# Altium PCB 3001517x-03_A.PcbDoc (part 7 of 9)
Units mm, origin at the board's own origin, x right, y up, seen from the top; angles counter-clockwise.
Board outline 100 x 72 mm, 10 copper layers (Top, GND_2, Signal_3, Signal_4, PWR_5, GND_6, Signal_7, Signal_8, GND_9, Bottom), stack 1.6 mm thick; 602 components, 497 nets, 2372 pads, 1602 vias.
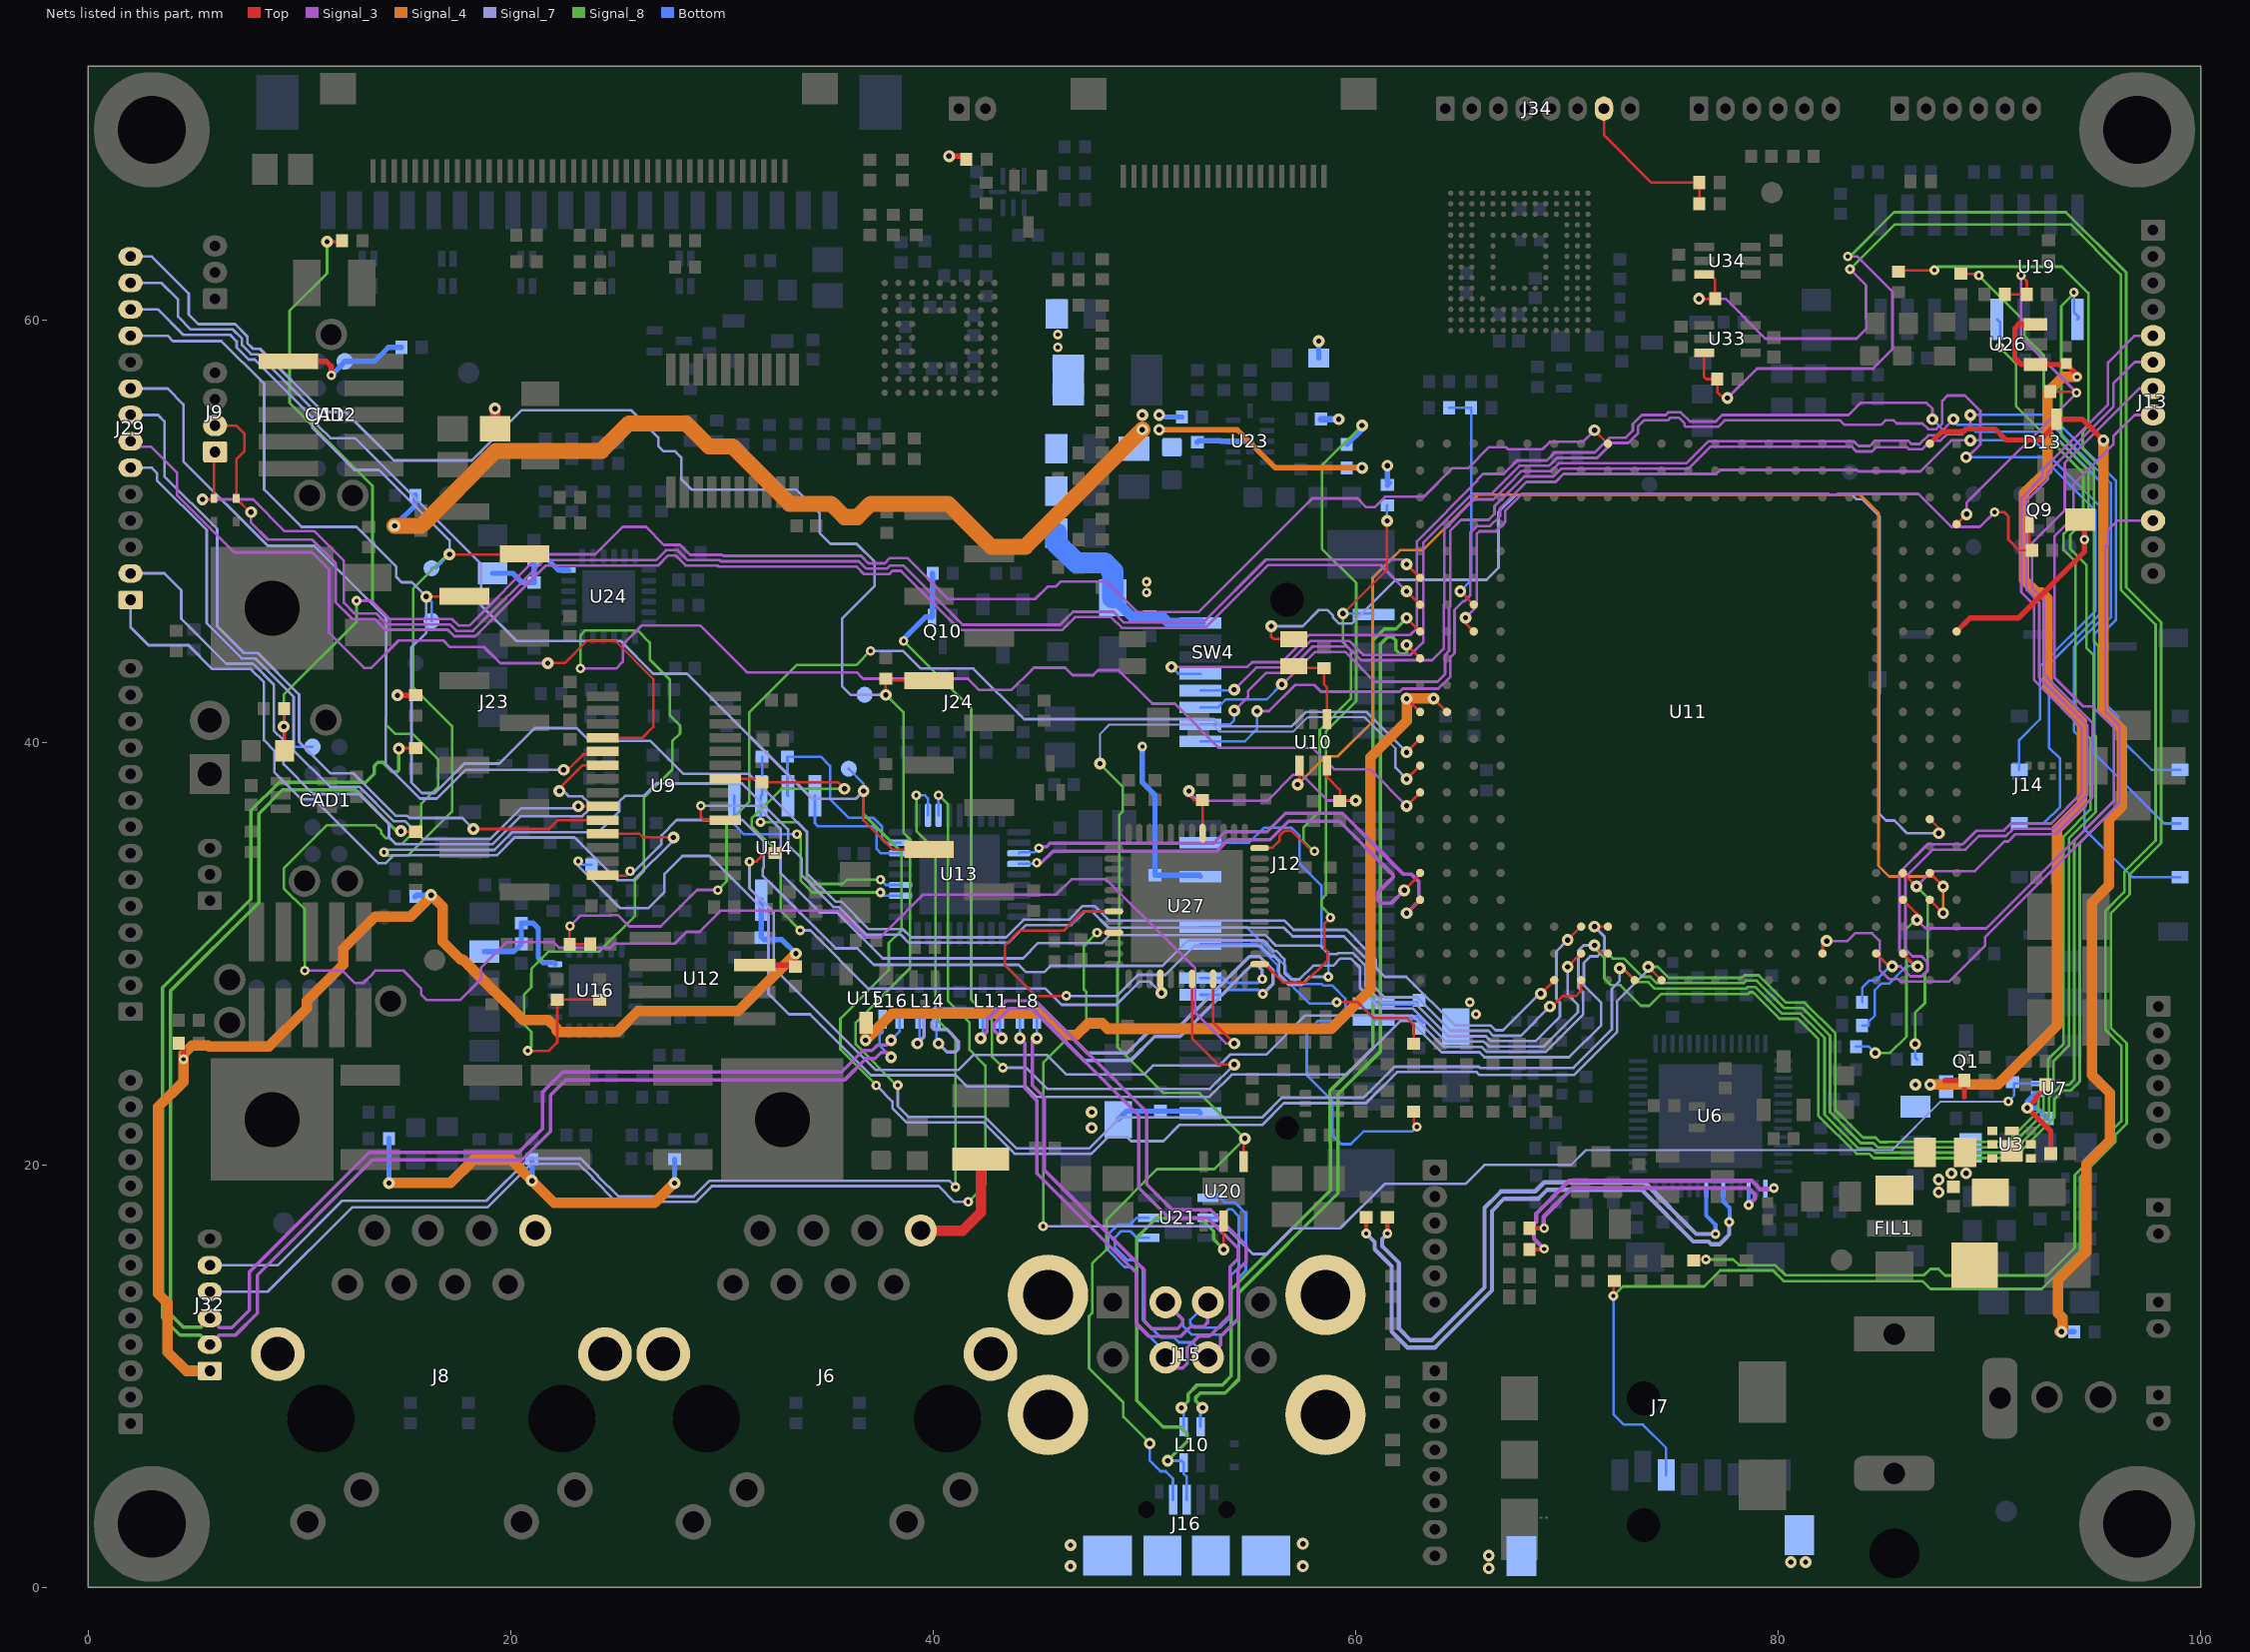
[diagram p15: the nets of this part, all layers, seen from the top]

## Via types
v1: diameter 0.56, hole 0.25, Top to Bottom, tented both sides, 1002 vias
v2: diameter 0.46, hole 0.2, Top to Bottom, tented both sides, 468 vias
v3: diameter 0.457, hole 0.2, Top to Bottom, tented both sides, 132 vias

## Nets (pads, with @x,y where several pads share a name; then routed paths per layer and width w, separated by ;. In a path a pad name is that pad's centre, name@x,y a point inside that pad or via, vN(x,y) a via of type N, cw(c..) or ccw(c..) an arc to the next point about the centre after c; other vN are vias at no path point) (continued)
OTGD_P: J16.3 L10.3 U20.5 | length 21.7
  Top w0.127: v1(53.75,16) U20.5@53.75,17.35
  Signal_8 w0.165: v1@51.101,6 52.016,6.915 52.016,7.284 51.7,7.6 50.88,7.6 49.632,8.848 49.632,16.552 50.548,17.468 52.652,17.468 53.268,16.852 53.268,16.482 v1(53.75,16)
  Bottom w0.127: v1(51.1,6) 51.75,6 L10.3@51.85,5.9 51.85,5.386 52,5.236 J16.3@52,4.15
PCIE_DIS_N/IO12: J12.20 U27.19 | length 37.3
  Top w0.119: v2(46.3,28) 44.85,28 43.4,29.45 43.4,30.4 44.1,31.1 46.2,31.1 47.1,32 U27.19@48.55,32
  Signal_7 w0.127: v2(46.3,28) 48.7,28 49.7,29 51,29 52.371,30.371 55.518,30.371 56.016,29.873 56.127,29.873 56.376,29.624 56.376,28.973 56.821,28.527 57.44,28.527 57.813,28.9 v2(58.7,28.9)
  Bottom w0.119: J12.20@52.65,35.25 54.95,35.25 55.667,35.966 56.95,35.966 57.35,35.566 57.35,34.25 58.385,33.215 58.385,30.376 58.7,30.061 v2(58.7,28.9)
PCIE_I2C_SCL: J12.30 R95.2 | length 22
  Top w0.119: R95.2@62.75,22.52 62.75,21.95 v2(62.9,21.8)
  Bottom w0.119: J12.30@52.65,31.25 54.843,31.25 56.685,29.408 56.685,29.128 57.246,28.566 58.393,28.566 58.476,28.484 58.905,28.484 59.516,27.872 59.516,27.116 59.2,26.8 58.2,26.8 57.683,26.283 57.683,24.25 58.908,23.025 58.908,21.392 59.316,20.984 59.773,20.984 60.367,21.578 62.678,21.578 v2(62.9,21.8)
PCIE_I2C_SDA: J12.32 R96.2 | length 12.8
  Top w0.119: v2(59.1,27.7) 60.1,27.7 60.85,26.95 62.443,26.95 62.75,26.643 R96.2@62.75,25.73
  Bottom w0.119: J12.32@52.65,30.45 55.295,30.45 56.3,29.445 56.3,29.15 57.816,27.634 59.033,27.634 v2(59.1,27.7)
PCIE_UIM_CLK: J12.12 J14.3 | length 72.5
  Signal_3 w0.127: v1(56.5,42.75) 56.55,42.75 58.086,44.286 59.495,44.286 60.906,42.875 63.88,42.875 64.231,43.225 64.231,44.136 64.424,44.33 64.424,46.379 64.475,46.429 64.475,50.012 64.992,50.529 66.295,50.529 66.575,50.809 66.575,51.183 67.98,52.588 69.363,52.588 69.735,52.96 75.76,52.96 76.8,54 83.475,54 83.7,53.775 84.445,53.775 84.645,53.976 86.1,53.976 86.2,53.875 86.8,53.875 87.209,54.285 87.685,54.285 88.1,54.7 88.825,54.7 89.1,54.975 v1(89.1,55.5)
  Bottom w0.119: J12.12@52.65,41.65 53.479,41.65 53.863,42.033 55.783,42.033 v1(56.5,42.75) ; v1(89.1,55.5) 92.874,55.5 96,52.374 96,45.808 95.294,45.102 95.294,42.019 96.1,41.213 96.1,40.275 97.675,38.7 J14.3@99.03,38.7
PCIE_UIM_DATA: J12.10 J14.7 | length 71.5
  Signal_3 w0.127: v1(54.25,42.5) 55.296,43.546 56.605,43.546 57.853,44.794 59.705,44.794 60.355,44.145 62.61,44.145 63.2,44.735 63.2,49.455 65.509,51.765 66.42,51.765 67.107,52.452 67.751,53.096 69.153,53.096 69.524,53.468 71.43,53.468 72.138,54.175 72.9,54.175 73.375,54.65 73.375,54.97 73.651,55.246 74.781,55.246 74.905,55.37 75.295,55.37 75.57,55.095 75.57,54.985 75.615,54.94 77.155,54.94 77.46,55.246 82.93,55.246 83.146,55.03 84.864,55.03 85.08,55.246 85.47,55.246 85.615,55.1 86.835,55.1 87.105,54.83 87.495,54.83 87.771,55.105 87.771,56.17 88.02,56.42 88.845,56.42 89.57,55.695 89.57,54.105 88.965,53.5 v1(88.9,53.5)
  Bottom w0.119: J12.10@52.65,42.45 54.2,42.45 v1(54.25,42.5) ; v1(88.9,53.5) 92.5,53.5 95.016,50.984 95.016,46.216 92.4,43.6 92.4,41.1 91.41,40.11 J14.7@91.41,38.7
PCIE_UIM_PWR: J12.8 J14.1 | length 78.5
  Signal_3 w0.127: v1(51.277,43.573) 54.873,43.573 55.1,43.8 56.5,43.8 57.786,45.086 62.586,45.086 62.9,45.4 62.9,49.515 65.755,52.369 65.755,52.43 66.03,52.706 67.002,52.706 67.646,53.35 69.048,53.35 69.419,53.722 71.325,53.722 72.033,54.429 72.795,54.429 73.121,54.755 73.121,55.075 73.545,55.5 74.675,55.5 74.8,55.624 75.4,55.624 75.83,55.194 77.05,55.194 77.355,55.5 83.334,55.5 83.905,56.07 87.03,56.07 87.3,55.8 v1(87.3,55.3)
  Bottom w0.119: v1(51.277,43.573) 51.599,43.25 J12.8@52.65,43.25 ; v1(87.3,55.3) 88.012,54.588 88.728,54.588 88.907,54.766 89.293,54.766 89.359,54.7 92.9,54.7 95.508,52.092 95.508,46.012 94,44.504 94,40.538 94.5,40.038 94.5,35.9 96.78,33.62 J14.1@99.03,33.62
PCIE_UIM_RST: J12.14 J14.2 | length 73.5
  Signal_3 w0.127: v1(54.25,41.5) 54.9,42.15 54.9,42.42 55.772,43.292 56.71,43.292 57.958,44.54 59.6,44.54 60.25,43.891 63.626,43.891 64.17,44.435 64.17,46.484 64.2,46.514 64.2,50.096 65.604,51.5 66.515,51.5 67.212,52.198 67.857,52.842 69.258,52.842 69.63,53.214 75.654,53.214 76.694,54.254 83.58,54.254 83.805,54.029 84.34,54.029 84.585,54.275 86.159,54.275 86.305,54.129 86.695,54.129 87.104,54.539 87.563,54.539 88.3,55.275 v1(88.3,55.3)
  Bottom w0.119: J12.14@52.65,40.85 54.05,40.85 54.25,41.05 v1(54.25,41.5) ; v1(88.3,55.3) 88.3,55.2 88.467,55.033 89.593,55.033 89.614,55.054 92.96,55.054 95.754,52.26 95.754,45.91 94.983,45.14 94.983,39.458 98.281,36.16 J14.2@99.03,36.16
PCIE_UIM_VPP: J12.16 J14.6 | length 72
  Signal_3 w0.127: v1(55.328,41.477) 55.893,41.477 57.137,42.72 58.037,42.72 58.358,42.4 62.075,42.4 62.22,42.546 63.91,42.546 64.485,43.12 64.485,44.031 64.678,44.225 64.678,46.274 65.089,46.685 65.15,46.685 65.426,46.96 65.426,49.89 65.424,49.891 65.424,49.924 65.665,50.166 65.674,50.166 65.749,50.241 66.365,50.241 66.829,50.704 66.829,51.078 68.085,52.334 69.469,52.334 69.84,52.706 77.078,52.706 77.273,52.9 83.734,52.9 83.805,52.829 86.729,52.829 88.2,54.3 v1(89.1,54.3)
  Bottom w0.119: J12.16@52.65,40.05 54.752,40.05 55.328,40.626 v1(55.328,41.477) ; v1(89.1,54.3) 92.1,54.3 95.262,51.138 95.262,46.114 92.821,43.673 92.821,39.758 93.35,39.229 93.35,36.95 92.56,36.16 J14.6@91.41,36.16
PCIE_VCC: C14.2 C22.2 C34.1 C35.1 C36.1 C37.2 C38.2 C39.2 C108.2 C115.2 C116.2 C117.2 C119.2 J12.2 J12.24 J12.39 J12.41 J12.52 L1.2 L29.1 R143.2 R241.2 | length 30.4
  Top w0.5: L29.1@19.25,54.85 v1(19.25,55.8)
  Bottom w0.25: C35.1@48.75,22.15 49.14,22.54 C38.2@50.75,22.54 52.56,22.54 J12.52@52.65,22.45 ; v2(49.9,39.8) 49.9,38.1 50.5,37.5 C22.2@50.5,33.71 52.59,33.71 J12.24@52.65,33.65 ; R143.2@58.25,58.2 v1(58.25,59) ; J12.41@60.85,26.85 60.85,26.982 63.018,26.982 63.2,26.8 ; J12.39@60.85,27.65 C39.2@62.86,27.65 ; R241.2@61.5,52.18 61.6,52.28 61.5,52.38 v1(61.5,53.1)
  Bottom w0.3: C108.2@58.36,55.3 v1(59.2,55.3)
  Bottom w0.5: C34.1@48.5,46.85 49.39,45.96 C37.2@50.25,45.96 50.84,45.96 51.15,45.65 J12.2@52.65,45.65
  Bottom w1: C117.2@45.825,49.9 45.825,49.455 46.78,48.5 48.1,48.5 48.5,48.1 C34.1@48.5,46.85
  other v1: 47.5,21.75 47.5,22.5
  other v2: 65.7,27.125 65.4,27.7 50.1,47.1 50.1,47.6 45.9,58.7 45.9,59.3
PCIE_VCC_EN/IO27: R141.1 U27.37 | length 33
  Top w0.125: U27.37@55.45,29.5 55.707,29.5 56.571,28.636 57.614,28.636 58.668,29.69 58.668,30.089 58.53,30.226 58.53,31.43 v3(58.8,31.7)
  Signal_8 w0.125: v3(58.8,31.7) 58.8,31.807 58.38,32.226 58.38,32.574 58.586,32.779 58.586,40.512 60.024,41.95 60.024,47.546 58.4,49.17 58.4,53.1 v1(60.3,55)
  Bottom w0.25: R141.1@59.58,54.1 60.3,54.82 v1(60.3,55)
PCIE_WAKE_N/IO38: J12.1 R241.1 U27.48 | length 23.5
  Top w0.119: U27.48@55.45,35 55.467,35.016 56.063,35.016 56.385,35.339 56.385,35.572 56.628,35.815 56.972,35.815 57.937,34.85 v3(58.05,34.85) ; v1(59.4,46.1) 61.5,48.2 61.485,48.215 v1(61.485,50.485)
  Signal_8 w0.127: v3(58.05,34.85) 57.985,34.85 57.53,35.305 57.53,35.97 58.3,36.741 58.3,40.591 59.771,42.061 59.771,44.367 59.4,44.737 v1(59.4,46.1)
  Bottom w0.119: v1(59.4,46.1) 60.8,46.1 J12.1@60.85,46.05 ; v1(61.485,50.485) 61.485,51.205 R241.1@61.5,51.22
PCM_CLK: J13.5 R192.1 U11.C20 | length 46.5
  Top w0.119: U11.C20@85.91,30.01 86.52,29.4 v1(86.6,29.4)
  Signal_3 w0.127: v1(86.6,29.4) 86.475,29.4 85.746,30.129 85.746,33.846 87.079,35.18 88.755,35.18 89.397,35.821 90.685,35.821 91.023,36.16 92.922,36.16 94.375,37.613 94.375,40.702 92.108,42.969 92.108,46.51 91.51,47.108 91.51,51.557 92.515,52.561 92.515,52.887 95.615,55.987 95.615,57.986 96.879,59.25 J13.5@97.75,59.25
  Bottom w0.119: R192.1@83.98,26.6 84.282,26.6 84.282,26.773 84.572,27.063 84.572,28.272 84.875,28.575 85.238,28.575 86.064,29.4 v1(86.6,29.4)
PCM_IN: J13.6 R195.1 U11.D20 | length 45.5
  Top w0.119: U11.D20@84.64,30.01 85.25,29.4 v1(85.4,29.4)
  Signal_3 w0.127: v1(85.4,29.4) 85.8,29.4 86.271,28.929 86.795,28.929 87.07,29.205 87.07,29.595 86.795,29.87 86.364,29.87 86.03,30.205 86.03,33.629 87.326,34.926 88.86,34.926 89.502,35.567 90.79,35.567 91.128,35.906 93.027,35.906 94.629,37.508 94.629,40.808 92.362,43.075 92.362,46.616 91.764,47.213 91.764,51.451 92.769,52.456 92.769,52.782 95.869,55.882 95.869,56.991 96.878,58 J13.6@97.75,58
  Bottom w0.119: R195.1@83.98,27.7 83.98,28.38 84.327,28.728 84.628,28.728 85.3,29.4 v1(85.4,29.4)
PCM_OUT: J13.7 R194.1 U11.C17 | length 43
  Top w0.119: U11.C17@85.91,33.82 v1(86.545,33.185)
  Signal_3 w0.127: v1(86.545,33.185) 87.27,33.91 89.309,33.91 90.713,35.313 90.895,35.313 91.234,35.652 93.132,35.652 94.883,37.403 94.883,40.913 92.616,43.18 92.616,46.721 92.018,47.319 92.018,49.421 93.57,50.973 93.57,53.224 97.096,56.75 J13.7@97.75,56.75
  Signal_8 w0.127: v1(86.485,25.725) 86.485,27.2 86.947,27.662 86.947,29.047 87.075,29.175 87.075,32.655 v1(86.545,33.185)
  Bottom w0.119: v1(86.485,25.725) 86.485,25.095 R194.1@86.58,25
PCM_SYNC: J13.8 R193.1 U11.C18 | length 44
  Top w0.119: U11.C18@85.91,32.55 86.573,31.887 v1(86.573,31.6)
  Signal_3 w0.127: v1(86.573,31.6) 86.973,31.2 89.855,31.2 95.9,37.245 95.9,40.694 94.894,41.7 94.455,41.7 93.079,43.076 93.079,49.76 93.975,50.656 93.975,52.21 95.87,54.105 95.87,54.492 96.878,55.5 J13.8@97.75,55.5
  Signal_8 w0.127: v1(84.6,25.3) 85.3,25.3 86.07,26.07 86.07,30.164 86.03,30.205 86.03,31.13 86.5,31.6 v1(86.573,31.6)
  Bottom w0.119: R193.1@83.68,25.6 84.3,25.6 v1(84.6,25.3)
POR_B: CAD1.10 R213.1 R257.1 U11.P1 | length 80
  Top w0.119: v1(9.25,40.75) 9.25,41.591 R257.1@9.259,41.6 ; R213.1@9.3,39.6 v1@9.3,40.7 ; v1(71.305,54.775) U11.P1@71.94,54.14
  Signal_3 w0.127: v3(12.7,46.7) 13.407,46.7 14.267,45.84 17.221,45.84 17.532,45.529 18.029,45.529 21.4,48.9 24,48.9 25.3,50.2 26.4,50.2 27.244,49.356 28.011,49.356 28.484,48.883 29.99,48.883 30.044,48.828 36.585,48.828 36.938,48.475 37.7,48.475 37.953,48.728 38.772,48.728 40.721,46.78 44.81,46.78 45.404,47.373 45.8,47.373 46.047,47.62 48.193,47.62 49.64,46.173 52.568,46.173 57.945,51.55 60.085,51.55 60.505,51.13 60.895,51.13 61.395,51.629 63.226,51.629 64.572,52.975 65.31,52.975 66.31,53.976 67.106,53.976 67.203,53.878 68.844,53.878 69.196,54.229 70.759,54.229 v1(71.305,54.775)
  Signal_8 w0.127: v1(9.25,40.75) 9.25,42.25 12.7,45.7 v3(12.7,46.7)
  Bottom w0.119: v1(9.25,40.75) 9.25,40.085 9.545,39.79 CAD1.10@10.615,39.79
PWR_EN/IO14: R22.2 U7.4 U27.21 | length 67.2
  Top w0.125: v2(47.75,31) U27.21@48.55,31
  Signal_8 w0.125: v2(45.2,17.1) 45.22,17.119 45.22,24.856 47.24,26.876 47.24,28.196 47.13,28.306 47.13,30.38 v2(47.75,31)
  Signal_7 w0.1: 67.6,20 70.2,20 70.9,20.7 85.4,20.7 87.7,23 v2(90.9,23)
  Signal_7 w0.125: v2(45.2,17.1) 53.809,17.1 55.127,15.782 55.782,15.782 57,17 59.277,17 61.377,19.1 65.2,19.1 66.1,20 67.6,20
  Bottom w0.1: v2(90.9,23) 91.17,23.27 R22.2@91.17,23.85
  Bottom w0.125: R22.2@91.17,23.85 U7.4@92.29,23.85
PWR_ON: Q9.G R212.2 U11.W8 | length 36
  Top w0.125: v1(65.2,45.9) 65.2,45.64 U11.W8@65.59,45.25 ; v2(90.25,50.9) 90.7,50.9 90.9,50.7 90.9,49.602 91.402,49.1 R212.2@92.02,49.1 91.9,49.22 Q9.G@91.9,50.31
  Signal_3 w0.125: v1(65.2,45.9) 65.73,46.43 65.73,49.864 65.854,49.987 66.63,49.987 67.082,50.439 67.082,50.627 67.082,50.973 67.874,51.765 82.37,51.765 82.405,51.73 82.794,51.73 82.829,51.765 86.635,51.765 88.2,50.2 89.55,50.2 v2(90.25,50.9)
QOW: J13.12 U11.F20 | length 35.7
  Top w0.125: U11.F20@82.1,30.01 82.1,30.4 v1(82.3,30.6)
  Signal_3 w0.125: v1(82.3,30.6) 83.277,30.6 83.647,30.97 84.448,30.97 84.805,30.612 84.805,29.23 85.236,28.8 85.664,28.8 85.787,28.676 88.076,28.676 89.8,30.4 89.8,30.787 96.154,37.141 96.154,40.798 95.5,41.452 95.5,49.284 95.606,49.39 95.606,50.031 96.075,50.5 J13.12@97.75,50.5
RF1_INT/NEXT: SW4.4 U11.B15 | length 53.8
  Top w0.119: v1(56,45.5) 56,45 56.115,44.885 SW4.4@57.06,44.885 ; U11.B15@87.18,36.36 87.7,35.84 87.604,35.745 v1(87.604,35.702)
  Signal_7 w0.127: v1(56,45.5) 57.492,45.5 58.263,46.27 58.653,46.27 58.928,45.995 58.928,45.906 59.205,45.629 59.829,45.629 61.901,47.701 66.201,47.701 66.764,48.264 66.764,50.914 67.577,51.727 83.488,51.727 83.705,51.511 83.989,51.511 84.8,50.7 84.8,42.315 84.78,42.295 84.78,36.625 85.105,36.3 85.5,36.3 86.1,35.7 86.102,35.702 v1(87.604,35.702)
RF_KILL: U10.4 U11.B17 U11.B18 | length 61.7
  Top w0.119: v1(57.25,38) 57.35,38.1 U10.4@57.35,38.9 ; U11.B18@87.18,32.55 v1(87.815,31.915) ; U11.B17@87.18,33.82 v1(87.815,33.185)
  Signal_4 w0.127: v1(57.25,38) 58.591,39.341 59.148,39.341 60.8,40.992 60.8,47.8 62.1,49.1 63.17,49.1 65.797,51.727 83.873,51.727 84.747,50.853 84.747,34.153 85.244,33.656 87.345,33.656 v1(87.815,33.185) v1(87.815,31.915)
RF_KILL_HW#: R231.2 SW4.3 U10.1 | length 4
  Top w0.119: SW4.3@57.06,43.615 57.155,43.52 R231.2@58.5,43.52 58.5,42.75 58.65,42.6 U10.1@58.65,41.1
RF_KILL_SW#/IO2: R232.2 R260.2 U10.6 U27.5 | length 14.4
  Top w0.119: v1(52.1,37.7) 52.1,37.5 52.33,37.27 R232.2@52.75,37.27 ; R232.2@52.73,37.25 R232.2@52.75,37.27 ; U27.5@52.75,35.7 R232.2@52.75,37.27 ; U10.6@58.65,38.9 58.65,38.35 59.25,37.75 R260.2@59.25,37.23 59.27,37.25 v1(60,37.25)
  Signal_3 w0.127: v1(52.1,37.7) 52.05,37.7 52.521,37.229 55.814,37.229 57.055,38.47 57.445,38.47 58.665,37.25 v1(60,37.25)
RS232_3_CTS_N: J29.9 U9.5 | length 37
  Top w0.119: v1(22.5,38.7) 22.7,38.7 23.425,39.425 24.2,39.425 U9.5@24.35,39.575 U9.5@24.35,39.62
  Signal_7 w0.127: J29.9@2,56.75 3.75,56.75 4.5,56 4.5,53.3 8.5,49.3 10.693,49.3 14.1,45.893 14.1,41.218 14.081,41.199 14.081,38.96 15.695,37.346 16.506,37.346 17.86,38.7 v1(22.5,38.7)
RS232_3_RTS_N: J29.8 U9.10 | length 36.2
  Top w0.119: v1(18.225,35.9) 21.8,35.9 22.225,36.325 U9.10@24.35,36.325
  Signal_7 w0.127: J29.8@2,55.5 3.3,55.5 3.6,55.2 3.6,52.6 6.1,50.1 6.1,45.5 7.367,44.232 8.011,44.232 9.974,42.269 9.974,40.026 11.47,38.53 12.555,38.53 14.56,36.524 15.1,36.524 15.2,36.424 17.701,36.424 v1(18.225,35.9)
RS232_3_RX: J29.7 U9.4 | length 38.5
  Top w0.119: v1(21.75,43.75) 22.55,43.75 23.6,44.8 24.952,44.8 26.75,43.002 26.75,40.742 26.233,40.225 U9.4@24.35,40.225
  Signal_3 w0.127: J29.7@2,54 2.95,54 4.2,52.75 4.2,51.7 6.9,49 10.6,49 11.4,48.2 11.4,45.183 13.052,43.531 13.399,43.531 14.693,44.824 16.8,44.824 17.111,44.514 18.737,44.514 19.5,43.75 v1(21.75,43.75)
RS232_3_TX: J29.6 U9.9 | length 34.5
  Top w0.119: v1(23.193,36.975) U9.9@24.35,36.975
  Signal_7 w0.127: J29.6@2,53 3,53 3.25,52.75 3.25,52.4 5.6,50.05 5.6,45.641 7.262,43.978 7.905,43.978 9.72,42.163 9.72,39.614 11.435,37.9 12.825,37.9 14.455,36.27 14.995,36.27 15.836,35.429 19.029,35.429 20.478,36.878 23.096,36.878 v1(23.193,36.975)
RS232_IOEXP_2_RX: J29.2 U9.6 | length 35.4
  Top w0.119: v1(22.3,37.7) 22.3,37.825 23.4,38.925 U9.6@24.35,38.925
  Signal_7 w0.127: J29.2@2,48 3.6,48 4.4,47.2 4.4,45.85 6.525,43.724 7.8,43.724 8.779,42.745 8.779,40.555 9.235,40.1 9.235,38.965 10.646,37.554 12.812,37.554 14.23,36.137 14.23,35.505 14.559,35.175 19.135,35.175 20.464,36.505 23.388,36.505 23.664,36.78 23.664,37.17 23.388,37.446 22.755,37.446 22.5,37.7 v1(22.3,37.7)
RS232_IOEXP_2_TX: J29.1 U9.11 | length 39.5
  Top w0.119: U9.11@24.35,35.675 26.088,35.675 26.263,35.5 v1(27.7,35.5)
  Signal_7 w0.127: J29.1@2,46.75 2,45.45 2.85,44.6 4.741,44.6 5.87,43.47 6.305,43.47 7.695,43.47 8.315,42.85 8.315,40.1 8.8,39.615 8.8,38.6 10.1,37.3 10.705,37.3 13.726,34.279 14.074,34.279 14.458,34.664 16.561,34.664 16.57,34.654 19.332,34.654 20.178,35.5 23.02,35.5 25.039,33.481 25.824,33.481 27.7,35.357 v1(27.7,35.5)
SD_CLK: R35.1 R245.2 U34.3 | length 97.1
  Top w0.119: R35.1@76,15.48 76.02,15.5 76.046,15.526 v2(76.579,15.526) ; v1(76.25,61) R245.2@77.02,61 77.02,61.905 76.775,62.15 U34.3@76.5,62.15
  Signal_3 w0.127: v1(76.25,61) 77.508,61 79.393,59.115 83.715,59.115 84.17,59.571 84.17,59.995 84.157,60.009 84.157,61.643 v2(83.4,62.4)
  Signal_8 w0.127: v2(76.579,15.526) 77.873,15.526 ; 77.874,15.525 77.899,15.5 78.145,15.254 79.868,15.254 80.343,14.779 86.914,14.779 87.205,15.07 87.595,15.07 87.903,14.762 92.73,14.762 94.038,16.07 94.038,19.52 95.703,21.184 95.703,21.519 96.246,22.062 96.246,25.645 95.496,26.395 95.496,32.021 96.387,32.912 96.387,33.862 97.875,35.351 97.875,45.575 96.223,47.227 96.223,62.143 93.843,64.522 85.522,64.522 v2(83.4,62.4)
SD_CMD: J7.3 R30.1 R243.2 U33.3 | length 116.2
  Top w0.119: v2(72.2,13.8) 72.2,14.45 R30.1@72.25,14.5 ; U33.3@76.5,58.45 76.5,57.3 76.6,57.2 R243.2@77.12,57.2 77.12,56.58 77.4,56.3 v1(77.6,56.3)
  Signal_3 w0.127: v1(77.6,56.3) 79,57.7 84.5,57.7 85.409,58.609 85.409,61.341 83.75,63 v2(83.3,63)
  Signal_8 w0.127: v2(72.2,13.8) 72.65,14.25 76.5,14.25 77.25,15 79.75,15 80.25,14.5 86.835,14.5 87.205,14.129 92.476,14.129 94.292,15.945 94.292,19.414 95.957,21.079 95.957,21.414 96.5,21.957 96.5,25.75 95.75,26.5 95.75,31.915 96.641,32.806 96.641,33.757 98.129,35.245 98.129,45.68 96.477,47.333 96.477,62.248 93.625,65.1 85.492,65.1 83.392,63 v2(83.3,63)
  Bottom w0.119: v2(72.2,13.8) 72.2,8.2 72.7,7.7 73.6,7.7 74.7,6.6 J7.3@74.7,5.325
SHLD: J6.8 J6.SHLD1 J6.SHLD2 J7.11 J7.12 J8.8 J8.SHLD1 J8.SHLD2 J15.SH1 J15.SH2 J15.SH3 J15.SH4 J16.6 J16.7 J16.8 J16.9 R55.2 | length 5.7
  Top w0.5: J6.8@39.41,16.89 41.39,16.89 42.257,17.757 42.257,20.268 R55.2@42.25,20.275
  other v1: 66.3,0.9 46.5,1 57.5,1 80.6,1.2 81.3,1.2 66.3,1.5 46.5,2 57.5,2.065
SPI1_IRQ_N: J34.7 R122.2 R273.2 | length 7.7
  Top w0.119: J34.7@71.75,70 71.75,68.75 74,66.5 R122.2@76.27,66.5 R273.2@76.27,65.5
SPKL_N: R276.1 U6.22 | length 29.6
  Top w0.2: v2(61.5,16.75) R276.1@61.5,17.52
  Signal_7 w0.2: v2(61.5,16.75) 61.247,16.497 61.247,16.153 62.05,15.35 62.05,12.25 62.6,11.7 63.6,11.7 66.1,14.2 66.1,17.966 66.781,18.647 66.884,18.75 68.5,18.75 68.925,19.175 73.679,19.175 76.125,16.729 77.029,16.729 v2(77.029,16.726)
  Bottom w0.2: U6.22@76.6,18.88 76.6,17.6 77.029,17.171 v2(77.029,16.726)
SPKL_P: R255.1 U6.20 | length 31.1
  Top w0.2: v2(60.5,16.75) R255.1@60.5,17.52
  Signal_7 w0.2: v2(60.5,16.75) 60.897,16.353 60.897,16.008 61.7,15.205 61.7,12.105 62.353,11.453 62.455,11.35 63.745,11.35 63.847,11.453 66.45,14.055 66.45,17.822 67.028,18.4 68.645,18.4 69.07,18.825 73.534,18.825 75.98,16.379 76.697,16.379 76.83,16.246 77.228,16.246 77.509,16.527 77.509,16.53 77.68,16.701 77.68,17.295 v2(77.685,17.3)
  Bottom w0.2: U6.20@77.4,18.88 77.4,18.276 77.711,17.965 77.711,17.326 v2(77.685,17.3)
SPKR_N: R278.1 U6.15 | length 15.1
  Top w0.2: R278.1@68.23,16 68.9,16 v2(68.925,16.025)
  Signal_3 w0.2: v2(68.925,16.025) 68.445,16.505 68.445,17.199 68.55,17.304 68.55,17.691 70.109,19.25 78.745,19.25 78.765,19.23 79.147,18.847 79.747,18.847 v2(79.8,18.9)
  Bottom w0.2: U6.15@79.4,18.88 79.78,18.88 v2(79.8,18.9)
SPKR_P: R277.1 U6.17 | length 13.3
  Top w0.2: R277.1@68.23,17 v2(68.925,17)
  Signal_3 w0.2: v2(68.925,17) 68.9,17.025 68.9,17.546 70.254,18.9 78.6,18.9 78.9,18.6 78.9,18.4 v2(78.6,18.1)
  Bottom w0.2: v2(78.6,18.1) U6.17@78.6,18.88
UART2_CTS_N/CAN2_TX: J24.5 J29.14 R145.2 TP12.1 U11.N21 U19.1 | length 190.4
  Top w0.119: v1(37.75,42.25) R145.2@37.75,43.02 37.845,42.925 J24.5@39.8,42.925 ; v1(72.5,29.3) 72.65,29.3 U11.N21@73.21,28.74
  Signal_8 w0.127: v1(37.75,42.25) 38.596,41.404 38.596,35.721 38.9,35.416 38.9,29.3 36.33,26.729 36.33,25.705 38.259,23.776 v3(38.324,23.776) ; v1(72.5,29.3) 72.65,29.3 73.3,28.651 73.851,28.651 74.156,28.346 78.478,28.346 78.553,28.42 78.92,28.42 80.169,27.171 81.042,27.171 82.2,26.013 82.2,22.384 83.805,20.779 84.408,20.779 84.615,20.571 85.384,20.571 85.391,20.578 91.062,20.578 92.822,22.338 92.822,23.205 93.395,23.778 93.754,23.778 94.022,24.046 94.022,35.337 95.9,37.215 95.9,40.694 95.174,41.42 95.174,44.552 94.953,44.774 94.953,52.955 93.4,54.507 93.4,60.65 94,61.25 v2(94,61.3)
  Signal_7 w0.127: J29.14@2,63 3,63 4.75,61.25 4.75,60.25 5.2,59.8 6.951,59.8 7.529,59.222 7.529,58.905 7.805,58.629 8.122,58.629 11.108,55.643 12.165,55.643 14.461,53.347 18.147,53.347 20.527,55.727 25.686,55.727 26.979,54.434 26.979,54.026 27.226,53.779 27.786,53.779 28.07,53.495 28.07,52.461 28.57,51.962 33.516,51.962 34.629,50.848 34.629,49.905 35.134,49.4 36.372,49.4 37.229,48.544 37.229,47.41 35.679,45.861 35.679,42.652 36.081,42.25 v1(37.75,42.25) ; v3(38.324,23.776) 38.324,22.782 38.836,22.27 42.465,22.27 43.955,20.78 47.38,20.78 48.846,22.246 55.568,22.246 56.5,23.178 60.378,23.178 61.847,24.647 65.827,24.647 65.88,24.594 70.309,24.594 72.126,26.411 72.126,28.334 72.5,28.708 v1(72.5,29.3)
  Bottom w0.119: 37.155,42.25 v1(37.75,42.25) ; v2(94,61.3) 94,60.365 94.25,60.115 U19.1@94.165,60.03
UART2_RTS_N/CAN2_RX: J24.9 J29.13 TP14.1 U11.M21 U19.4 | length 179.8
  Top w0.119: v1(36.7,37.7) 36.684,37.684 36.684,36.316 38.075,34.925 J24.9@39.8,34.925 ; v1(73.845,29.375) U11.M21@74.48,28.74
  Signal_8 w0.127: v1(36.7,37.7) 36.679,37.68 36.679,36.621 38.5,34.8 38.5,31.1 37.9,30.5 37.9,29.225 35.6,26.925 35.6,25.465 v3(37.3,23.765) ; v1(73.845,29.375) 74.3,29.375 74.821,28.854 78.268,28.854 78.389,28.975 79.084,28.975 80.38,27.679 81.252,27.679 82.708,26.224 82.708,22.594 84.016,21.287 84.619,21.287 84.826,21.079 85.174,21.079 85.181,21.086 90.852,21.086 92.314,22.548 92.314,23.416 92.776,23.878 92.776,25 93.514,25.738 93.514,35.547 94.782,36.816 94.782,40.19 94.079,40.893 94.079,48.551 93.516,49.114 93.516,49.87 94.445,50.798 94.445,52.744 91.261,55.928 91.261,56.061 91.262,56.062 91.262,57.938 v3(90.5,58.7)
  Signal_7 w0.127: J29.13@2,61.75 3.45,61.75 4.25,60.95 4.25,60.15 4.854,59.546 6.846,59.546 7.275,59.117 7.275,58.8 7.7,58.375 8.017,58.375 10.854,55.538 10.854,55.005 11.459,54.4 12.619,54.4 18.6,48.419 18.6,46.475 20.275,44.8 25.2,44.8 26.744,43.256 28.342,43.256 34.268,37.33 36.33,37.33 v1(36.7,37.7) ; v3(37.3,23.765) 38.07,22.995 38.07,22.676 38.731,22.016 42.359,22.016 43.85,20.526 47.485,20.526 48.259,21.3 49.2,21.3 49.371,21.13 50.895,21.13 51.658,21.893 55.574,21.893 56.605,22.924 60.483,22.924 61.952,24.393 65.721,24.393 65.862,24.252 70.327,24.252 72.38,26.306 72.38,27.762 73.845,29.227 v1(73.845,29.375)
  Bottom w0.119: TP14.1@36,38.75 36.7,38.05 v1(36.7,37.7) ; U19.4@90.355,60.03 90.5,59.885 v3(90.5,58.7)
UART2_RX: J23.2 J29.12 TP10.1 U11.R21 | length 110.8
  Top w0.119: v1(17.1,48.9) 20.675,48.9 J23.2@20.65,48.925 ; v1(69.2,27.5) 69.303,27.5 69.803,28 70.438,28 70.67,28.232 U11.R21@70.67,28.74
  Signal_8 w0.127: v2(14,34.8) 14,34.702 13.949,34.651 15.141,34.651 17.22,36.73 17.22,40.779 15.375,42.625 15.375,47.275 17,48.9 v1(17.1,48.9)
  Signal_7 w0.127: J29.12@2,60.5 3.292,60.5 4.5,59.292 6.708,59.292 7.021,58.979 7.021,58.695 7.595,58.121 7.879,58.121 10.6,55.4 10.6,54.9 12.6,52.9 13.76,52.9 17.1,49.56 v1(17.1,48.9) ; v2(14,34.8) 14.118,34.918 16.666,34.918 16.676,34.908 19.226,34.908 20.072,35.754 24.154,35.754 25.13,36.729 25.13,37.195 25.405,37.47 26.3,37.47 26.88,38.05 30.953,38.05 33.129,35.874 33.129,35.145 33.776,34.499 33.776,33.7 35.267,32.208 35.535,32.208 36.843,30.9 38.465,30.9 38.849,30.516 43.552,30.516 44.387,31.352 46.532,31.352 47.176,31.995 47.524,31.995 48.287,31.233 56.601,31.233 57.013,30.82 59.438,30.82 60.708,29.551 60.708,28.592 61.371,27.929 62.902,27.929 64.483,26.348 66.278,26.348 66.511,26.116 67.815,26.116 v1(69.2,27.5)
  Bottom w0.119: TP10.1@16.25,48.25 16.45,48.25 v1(17.1,48.9)
UART2_TX: J23.3 J29.11 TP11.1 U11.T21 | length 99.6
  Top w0.119: v1(16,46.9) 17.775,46.9 J23.3@17.8,46.925 ; v1(68.765,28.105) U11.T21@69.4,28.74
  Signal_7 w0.127: J29.11@2,59.25 3.75,59.25 4,59 6.3,59 8.321,56.979 8.321,51.968 10.089,50.2 12.7,50.2 14.581,48.319 14.581,47.826 14.826,47.581 15.319,47.581 v1(16,46.9) 16,45.2 15.3,44.5 15.3,38.1 15.8,37.6 16.4,37.6 17.8,39 19.45,39 21.125,40.675 23.12,40.675 23.72,40.075 26.606,40.075 28.172,38.509 31.285,38.509 34.03,35.765 34.03,33.805 35.373,32.462 35.64,32.462 36.948,31.154 38.571,31.154 38.954,30.77 43.447,30.77 44.282,31.606 46.427,31.606 47.071,32.249 47.629,32.249 48.311,31.568 56.625,31.568 57.063,31.129 59.571,31.129 60,30.7 60,30.678 60.962,29.716 60.962,29.316 61.373,28.905 62.395,28.905 64.698,26.602 66.383,26.602 66.616,26.37 66.964,26.37 68.7,28.105 v1(68.765,28.105)
  Bottom w0.119: v1(16,46.9) 16.25,46.65 TP11.1@16.25,45.75
UART3_CTS_N/CAN1_TX: R77.1 R125.1 U11.P19 | length 141.3
  Top w0.119: v1(71.305,31.28) U11.P19@71.94,31.28 ; R77.1@88.65,62.18 89.42,62.18 v2(89.5,62.1)
  Signal_8 w0.127: v1(71.305,31.28) 71.776,30.81 71.776,30.166 72.171,29.77 72.695,29.77 73.561,28.905 73.956,28.905 74.261,28.6 78.373,28.6 78.495,28.721 78.979,28.721 80.275,27.425 81.147,27.425 82.454,26.118 82.454,22.489 83.911,21.033 84.513,21.033 84.72,20.825 85.279,20.825 85.286,20.832 90.957,20.832 92.568,22.443 92.568,23.311 93.03,23.773 93.03,24.895 93.768,25.633 93.768,35.442 95.036,36.711 95.036,40.295 94.92,40.411 94.92,44.146 94.6,44.467 94.6,48.389 93.827,49.162 93.827,49.822 94.699,50.693 94.699,52.849 92.578,54.97 92.578,58.322 91.661,59.239 91.661,59.939 v2(89.5,62.1)
  Signal_7 w0.127: v3(23.193,34.375) 23.193,34.148 25.189,32.152 26.507,32.152 27.274,32.919 27.274,33.769 28.126,34.62 29.416,34.62 32.2,31.837 32.2,28.1 33.17,27.13 34.17,27.13 37.054,24.246 41.054,24.246 41.58,23.72 44.379,23.72 44.877,23.223 53.08,23.223 54.132,24.275 59.574,24.275 62.12,26.82 62.574,26.82 64.062,25.332 65.857,25.332 66.09,25.1 70.1,25.1 71.62,26.62 71.62,27.68 70.8,28.5 70.8,29.565 71.105,29.87 71.45,29.87 71.785,30.206 71.785,30.8 v1(71.305,31.28)
  Bottom w0.119: v3(23.193,34.375) 23.368,34.2 R125.1@23.82,34.2
UART3_RTS_N/CAN1_RX: R123.1 R155.1 U11.P20 | length 136.2
  Top w0.119: v2(31.3,34.35) 31.6,34.35 32.02,34.77 R155.1@32.5,34.77 ; v1(71.305,30.391) 71.686,30.01 U11.P20@71.94,30.01 ; R123.1@85.7,62.28 85.77,62.35 v2(87.4,62.35)
  Signal_8 w0.127: v1(71.305,30.391) 71.305,30.277 71.776,29.807 71.776,29.6 71.775,28.825 72.092,28.508 72.527,28.508 73.505,27.53 73.895,27.53 74.457,28.092 78.584,28.092 78.658,28.166 78.815,28.166 80.064,26.917 80.936,26.917 81.904,25.95 81.904,25.295 81.9,25.291 81.9,22.325 83.7,20.525 84.303,20.525 84.51,20.317 85.49,20.317 85.497,20.324 91.167,20.324 93.076,22.233 93.076,23.1 93.5,23.524 93.859,23.524 94.276,23.941 94.276,35.231 96.154,37.11 96.154,40.8 95.428,41.525 95.428,44.657 95.207,44.879 95.207,53.11 94.422,53.895 94.422,54.705 94.688,54.971 94.688,61.269 93.436,62.52 87.571,62.52 v2(87.4,62.35)
  Signal_7 w0.127: v2(31.3,34.35) 31.3,33.096 32.454,31.942 32.454,29.311 37.265,24.5 41.2,24.5 41.9,25.2 45.4,25.2 46.32,24.28 49.98,24.28 50.4,24.7 53.535,24.7 54.055,25.22 55.767,25.22 57.621,27.074 62.679,27.074 64.168,25.586 65.962,25.586 66.195,25.354 69.007,25.354 70.774,27.121 70.774,28.166 70.546,28.395 70.546,30.146 70.791,30.391 v1(71.305,30.391)
UART3_RX: U9.19 U11.R19 | length 55
  Top w0.119: v2(29,37) 29,36.465 29.14,36.325 U9.19@30.15,36.325 ; v1(70.035,30.645) U11.R19@70.67,31.28
  Signal_7 w0.127: v2(29,37) 31.645,37 32.78,35.865 32.78,33.805 34.631,31.954 35.43,31.954 37.604,29.78 44.255,29.78 44.975,30.5 48,30.5 48.379,30.879 55.729,30.879 56.226,30.381 58.325,30.381 58.726,29.98 59.124,29.98 59.169,30.024 59.875,30.024 60.454,29.446 60.454,28.487 61.265,27.675 62.797,27.675 64.378,26.094 66.173,26.094 66.405,25.862 68.512,25.862 69.67,27.02 69.67,27.695 69.5,27.865 69.5,30.11 v1(70.035,30.645)
UART3_TX: U9.14 U11.R20 | length 59.9
  Top w0.119: U9.14@24.35,33.725 24.375,33.7 25.45,33.7 v3(25.65,33.9) ; v1(70.035,29.375) U11.R20@70.67,30.01
  Signal_7 w0.127: v3(25.65,33.9) 25.85,33.9 27.135,35.185 27.135,35.6 27.859,36.324 30.961,36.324 31.981,35.304 31.981,34.076 31.929,34.024 31.929,33.676 32.176,33.43 32.205,33.43 35.384,30.25 36.415,30.25 37.195,29.47 44.05,29.47 44.396,29.125 45.254,29.125 45.549,29.42 50.85,29.42 52.054,30.625 55.624,30.625 56.121,30.127 56.232,30.127 56.63,29.73 56.63,29.078 56.926,28.781 57.335,28.781 57.985,29.431 58.935,29.431 59.274,29.77 59.77,29.77 60.2,29.34 60.2,28.382 61.186,27.396 62.717,27.396 64.273,25.84 66.068,25.84 66.3,25.608 68.902,25.608 70.52,27.226 70.52,27.58 70.035,28.065 v1(70.035,29.375)
UART5_RX: D6.2 J9.2 U11.AA7 | length 70.6
  Top w0.119: J9.2@6,55 7,55 7.4,54.6 7.4,53.8 7,53.4 D6.2@7,51.55 7.65,50.9 v1(7.7,50.9) ; v1(62.415,47.155) U11.AA7@63.05,46.52
  Signal_3 w0.127: v1(7.7,50.9) 7.7,50.4 8.5,49.6 10.6,49.6 11.7,48.5 11.7,46.641 12.495,45.846 13.543,45.846 14.056,45.332 17.01,45.332 17.321,45.021 18.315,45.021 21.664,48.371 26.975,48.371 27.452,48.848 27.801,48.848 28.274,48.375 29.779,48.375 29.833,48.32 36.374,48.32 36.727,47.967 37.91,47.967 38.063,48.12 38.474,48.12 41.279,45.315 46.102,45.315 46.715,45.928 48.425,45.928 48.934,45.42 52.88,45.42 55.861,48.4 61.17,48.4 v1(62.415,47.155)
UART5_TX: D7.2 J9.1 U11.AA6 | length 69.4
  Top w0.119: v1(5.4,51.5) 5.9,51.5 D7.2@5.95,51.55 5.95,53.7 J9.1@6,53.75 ; v1(62.415,48.425) U11.AA6@63.05,47.79
  Signal_3 w0.127: v1(5.4,51.5) 7.8,51.5 9.3,50 10.7,50 12.1,48.6 12.1,46.6 12.6,46.1 13.648,46.1 14.162,45.586 17.116,45.586 17.427,45.276 18.21,45.276 21.559,48.625 26.87,48.625 27.347,49.102 27.906,49.102 28.379,48.629 29.885,48.629 29.939,48.574 36.479,48.574 36.832,48.221 37.805,48.221 37.959,48.375 38.578,48.375 41.385,45.569 45.997,45.569 46.61,46.182 48.531,46.182 49.04,45.674 52.775,45.674 55.756,48.654 62.186,48.654 v1(62.415,48.425)
UART_PWR/IO18: R127.2 U9.22 U27.28 | length 36.3
  Top w0.119: U9.22@30.15,38.275 31.745,38.275 R127.2@31.9,38.12 35.48,38.12 v1(35.8,37.8)
  Signal_8 w0.127: v2(33.7,31.1) 32.78,32.02 32.78,34.676 31.405,36.051 31.405,36.399 32.805,37.8 v1(35.8,37.8)
  Signal_7 w0.127: v2(33.7,31.1) 34.175,31.1 36.929,28.346 45.313,28.346 46.08,27.579 48.664,27.579 49.76,28.675 50.264,28.675 v1(50.8,28.139)
USB_OTG_D_N: L10.1 U11.AA9 | length 44.8
  Top w0.127: v1(62.415,44.615) U11.AA9@63.05,43.98
  Signal_8 w0.165: v1(52.75,8.5) 52.434,8.816 52.434,9 52.634,9.2 53.82,9.2 54.468,9.848 54.468,13.948 59.168,18.648 59.168,21.21 59.16,21.218 59.16,23.36 61.181,25.381 61.181,43.762 61.181,44.663 61.518,45 61.725,45 61.9,44.825 61.9,44.375 62.1,44.175 62.325,44.175 62.415,44.265 v1(62.415,44.615)
  Bottom w0.127: L10.1@52.65,7.6 52.65,8.4 v1(52.75,8.5)
USB_OTG_D_P: L10.4 U11.AA8 | length 44.7
  Top w0.127: v1(62.415,45.885) U11.AA8@63.05,45.25
  Signal_8 w0.165: v1(51.75,8.5) 52.066,8.816 52.066,9.152 52.482,9.568 53.668,9.568 54.1,10 54.1,14.1 58.8,18.8 58.8,21.058 58.792,21.066 58.792,23.513 60.813,25.534 60.813,44.816 61.366,45.368 61.898,45.368 v1(62.415,45.885)
  Bottom w0.127: v1(51.75,8.5) 51.85,8.4 L10.4@51.85,7.6
USB_OTG_ID: J16.4 U11.AA13 U20.1 | length 65.6
  Top w0.125: U20.1@54.7,20.15 54.7,21.2 v1(54.75,21.25) ; v1(62.415,38.265) U11.AA13@63.05,38.9
  Signal_8 w0.125: v1(47.9,39) 47.9,38.97 48.846,38.024 48.849,38.024 48.97,37.904 48.97,36.72 48.815,36.565 48.815,30.17 48.814,29.62 48.722,29.528 48.722,25.569 50.891,23.4 52.6,23.4 v1(54.75,21.25) 53.3,19.8 50.6,19.8 48.2,17.4 48.2,16 47.525,15.325 47.525,12.982 47.374,12.832 47.374,10.376 49,8.75 49,8.065 v1(50.25,6.815)
  Signal_7 w0.1: v1(47.9,39) 47.9,40.4 48.349,40.849 53.208,40.849 53.542,40.514 57.053,40.514 57.717,41.178 57.778,41.178 57.8,41.2 60.4,41.2 61.88,39.72 61.88,38.8
  Signal_7 w0.125: 61.88,38.8 v1(62.415,38.265)
  Bottom w0.125: v1@50.25,6.75 50.25,5.999 50.747,5.502 50.998,5.502 51.35,5.15 J16.4@51.35,4.15
USB_OTG_OC: R16.2 R118.1 U11.AA14 | length 81.3
  Top w0.125: v2(20.8,25.4) 21.8,25.4 22.2,25.8 R118.1@22.2,27.82 R16.2@24.2,27.82 ; v1(62.415,36.995) U11.AA14@63.05,37.63
  Signal_3 w0.125: v2(23.3,43.5) 24.987,43.5 25.3,43.813 25.3,44.632 26.206,45.538 28.962,45.538 31.181,43.319 36.374,43.319 36.619,43.074 36.675,43.018 41.638,43.018 42.18,42.476 43.695,42.476 44.646,43.428 44.67,43.452 44.756,43.538 46.249,43.538 46.606,43.18 47.574,43.18 47.813,43.419 48.781,43.419 50.02,42.18 50.369,41.831 51.439,41.831 53.533,39.738 57.97,39.738 58.974,38.734 60.677,38.734 v1(62.415,36.995)
  Signal_8 w0.125: v2(20.8,25.4) 20.97,25.57 20.97,26.301 20.628,26.642 20.628,28.064 20.97,28.406 20.97,29.062 20.98,29.072 20.98,29.274 21.807,30.1 24.193,30.1 25.876,31.783 25.876,33.476 26.3,33.9 26.3,37.358 27.643,38.701 27.643,40.052 28.018,40.427 28.018,40.773 28,40.791 28,40.826 27.526,41.299 27.526,42.98 26.58,43.926 26.58,44.72 26,45.3 23.525,45.3 23.3,45.075 v2(23.3,43.5)
USB_OTG_PWR: R15.1 R80.1 U11.AA12 | length 54.8
  Top w0.125: v2(22.8,31.3) 22.78,31.28 R80.1@22.78,30.436 22.794,30.45 R15.1@23.77,30.45 ; v1(62.415,39.535) U11.AA12@63.05,40.17
  Signal_3 w0.125: v2(22.8,31.3) 23.293,31.793 24.7,31.793 24.726,31.819 25.074,31.819 25.6,31.293 27.1,31.293 28.58,32.774 28.826,33.019 29.174,33.019 29.78,33.019 v2(29.8,33)
  Signal_8 w0.125: v2(29.8,33) 30.217,33.417 30.217,36.117 31.292,37.192 31.292,41.428 33.537,43.673 36.373,43.673 v2(37.032,44.332)
  Signal_7 w0.125: v2(37.032,44.332) 38.568,44.332 39.4,43.5 41.9,43.5 44.3,41.1 53.295,41.1 53.642,40.754 56.954,40.754 57.64,41.44 60.511,41.44 v1(62.415,39.535)
USB_OTG_VBUS: U11.AA11 U11.Y11 U15.D | length 44.3
  Top w0.125: v1(62.415,42.075) U11.AA11@63.05,41.44 ; v1(63.685,42.075) U11.Y11@64.32,41.44
  Top w0.5: v1(36.8,25.9) 36.8,26.7 U15.D@36.825,26.725
  Signal_4 w0.5: v1(36.8,25.9) 38.057,27.157 45.214,27.157 46.228,26.143 46.772,26.143 47.335,26.706 47.994,26.706 48.257,26.443 58.843,26.443 60.7,28.3 60.7,39.3 62.415,41.015 v1(62.415,42.075) v1(63.685,42.075)
USB_PWR/IO21: Q10.G R69.2 U27.31 | length 43.3
  Top w0.121: U27.31@52.25,28.8 52.25,26 53.5,24.75 v1(54.25,24.75)
  Signal_8 w0.125: v3(38.6,44.8) 41.8,41.6 41.8,27.817 42.78,26.837 42.78,25.12 v3(43.3,24.6)
  Signal_7 w0.125: v3(43.3,24.6) 44.4,24.6 45.4,23.6 53.1,23.6 v1(54.25,24.75)
  Bottom w0.25: v3(38.6,44.8) 38.6,44.9 39.64,45.94 Q10.G@39.95,45.94 39.97,45.96 R69.2@39.97,48
USBH1_D_N: J15.A2 L8.2 U21.1 | length 31.8
  Signal_3 w0.165: v1(44.9,26) 44.7,25.8 44.7,23.763 45.268,23.195 45.268,19.752 50,15.02 50,12.6 50.35,12.25 51.566,12.25 51.816,12.5 51.816,12.684 J15.A2@51,13.5
  Bottom w0.127: v1(44.9,26) L8.2@44.9,26.9 ; J15.A2@51,13.5 51.835,12.665 51.835,12.363 52.228,11.97 53.737,11.97 54.43,12.663 54.43,14.63 54.8,15 54.8,17.7 54.27,18.23 53.784,18.23 53.563,18.45 U21.1@53,18.45
USBH1_D_P: J15.A3 L8.3 U21.2 | length 31.8
  Signal_3 w0.165: v1(44.1,26) 44.332,25.768 44.332,23.61 44.9,23.042 44.9,19.6 49.632,14.868 49.632,12.448 50.198,11.882 51.718,11.882 52.184,12.348 52.798,12.348 53,12.55 J15.A3@53,13.5
  Bottom w0.127: v1(44.1,26) L8.3@44.1,26.9 ; J15.A3@53,13.5 52.165,12.665 52.165,12.5 52.365,12.3 53.6,12.3 54.1,12.8 54.1,14.767 54.47,15.137 54.47,17.563 54.133,17.9 53.963,17.9 53.563,17.5 U21.2@53,17.5
USBH1_OC_N: R65.1 U13.13 U14.2 | length 12.4
  Signal_8 w0.125: v2(31.825,36.225) 33.568,36.225 34,35.793 34,33.6 34.3,33.3 35.7,33.3 35.9,33.5 v2(37.5,33.5)
  Bottom w0.125: v2(31.825,36.225) 31.825,37.44 U14.2@31.855,37.47 31.9,37.515 R65.1@31.9,39.32 ; v2(37.5,33.5) 37.75,33.25 U13.13@38.45,33.25
USBH1_PWR_EN: U13.12 U14.1 | length 11.8
  Signal_8 w0.125: v2(33.55,35.65) 33.72,35.48 33.72,33.455 34.275,32.9 v2(37.5,32.9)
  Bottom w0.125: U14.1@30.585,37.47 30.585,36.115 31.05,35.65 v2(33.55,35.65) ; v2(37.5,32.9) 37.65,32.75 U13.12@38.45,32.75
USBH2_D_N: J15.B2 L11.2 U21.5 | length 37.8
  Signal_3 w0.165: v1(43.25,26) 42.9,26.35 42.9,26.7 43.6,27.4 44.68,27.4 49.732,22.348 49.732,18.923 51.155,17.5 52.98,17.5 54.432,16.048 54.432,15.552 54.062,15.182 54.062,12.882 53.08,11.9 52.575,11.9 52.025,11.35 52.025,10.6 51.8,10.375 51.505,10.375 J15.B2@51,10.88
  Bottom w0.127: L11.2@43.15,26.9 43.15,26.1 v1(43.25,26) ; U21.5@50.2,17.5 49.637,17.5 49.327,17.19 48.763,17.19 48.27,16.697 48.27,15.963 49.063,15.17 49.4,15.17 49.6,14.97 49.6,12.533 51,11.133 J15.B2@51,10.88
USBH2_D_P: J15.B3 L11.3 U21.4 | length 37.7
  Signal_3 w0.165: v1(42.25,26) 42.532,26.282 42.532,26.852 43.448,27.768 44.832,27.768 50.1,22.5 50.1,19.075 51.307,17.868 53.132,17.868 54.8,16.2 54.8,15.4 54.43,15.03 54.43,12.73 53.6,11.9 53.6,11.48 J15.B3@53,10.88
  Bottom w0.127: v1(42.25,26) 42.35,26.1 L11.3@42.35,26.9 ; U21.4@50.2,16.55 49.637,16.55 49.327,16.86 48.9,16.86 48.6,16.56 48.6,16.1 49.2,15.5 49.537,15.5 49.93,15.107 49.93,12.67 50.768,11.833 51.395,11.833 51.627,11.6 52.28,11.6 J15.B3@53,10.88
USBH2_OC_N: R66.1 U13.17 U14.3 | length 10.2
  Bottom w0.125: U14.3@33.125,37.47 33.1,37.495 R66.1@33.1,39.32 34.68,39.32 35.113,38.887 35.113,37.312 36,36.425 37.175,36.425 37.577,36.023 37.577,35.423 37.75,35.25 U13.17@38.45,35.25
USBH2_PWR_EN: U13.16 U14.4 | length 6.4
  Bottom w0.125: U14.4@34.395,37.47 34.395,36.18 34.55,36.025 37.125,36.025 37.325,35.825 37.325,34.95 37.525,34.75 U13.16@38.45,34.75
USBH3_D_N: J12.36 L14.2 | length 26.6
  Signal_7 w0.165: v1(40.25,25.75) 40.65,25.35 41.05,25.35 41.2,25.5 41.2,25.85 40.65,26.4 40.05,26.4 39.934,26.516 39.934,26.75 40.184,27 45.08,27 47.148,24.932 49.34,24.932 50.483,26.075 51.694,26.075 55.119,29.5 55.3,29.5 55.575,29.225 v2(55.575,28.8)
  Bottom w0.127: L14.2@40.15,26.9 40.15,25.85 v1(40.25,25.75) ; J12.36@52.65,28.85 53.714,28.85 53.949,28.615 55.39,28.615 v2(55.575,28.8)
USBH3_D_P: J12.38 L14.3 | length 26.7
  Signal_7 w0.165: v1(39.25,25.75) 39.566,26.066 39.566,26.902 40.032,27.368 45.232,27.368 47.3,25.3 49.188,25.3 50.33,26.443 51.542,26.443 54.967,29.868 55.452,29.868 56.09,29.23 56.09,28.57 55.62,28.1 v2(55.6,28.1)
  Bottom w0.127: v1(39.25,25.75) 39.35,25.85 L14.3@39.35,26.9 ; J12.38@52.65,28.05 53.714,28.05 53.949,28.285 55.415,28.285 v2(55.6,28.1)
USBH4_D_N: J32.3 L16.2 R129.1 | length 77.8
  Top w0.127: v1(14.8,35.8) 14.77,35.77 R129.1@15.5,35.77
  Signal_3 w0.165: J32.3@5.75,12.75 6.2,12.3 6.8,12.3 7.632,13.132 7.632,14.932 13.3,20.6 20.38,20.6 21.513,21.733 21.513,23.452 22.461,24.4 35.664,24.4 36.674,25.41 36.697,25.41 37.103,25.41 37.376,25.684 37.784,25.684 v1(38,25.9)
  Signal_8 w0.165: J32.3@5.75,12.75 5.309,12.309 4.5,12.309 3.888,12.921 3.888,28.238 8.068,32.418 8.068,36.629 9.189,37.75 12.65,37.75 14.6,35.8 v1(14.8,35.8)
  Bottom w0.127: v1(38,25.9) 38.4,26.3 L16.2@38.4,26.9
USBH4_D_P: J32.2 L16.3 R102.1 | length 80.9
  Top w0.127: v1(14.7,39.7) 14.73,39.73 R102.1@15.5,39.73
  Signal_3 w0.165: J32.2@5.75,11.5 6.182,11.932 6.952,11.932 8,12.98 8,14.78 13.452,20.232 20.532,20.232 21.881,21.581 21.881,23.3 22.613,24.032 35.816,24.032 36.826,25.042 37.255,25.042 37.529,25.316 37.784,25.316 v1(38,25.1)
  Signal_8 w0.165: J32.2@5.75,11.5 5.309,11.941 4.348,11.941 3.52,12.768 3.52,28.391 7.7,32.57 7.7,36.782 9.036,38.118 13.136,38.118 13.527,38.51 13.527,38.877 13.7,39.05 13.95,39.05 14.4,38.6 14.625,38.6 14.7,38.675 v1(14.7,39.7)
  Bottom w0.127: L16.3@37.6,26.9 37.6,26.273 37.454,26.126 37.454,25.674 38,25.127 v1(38,25.1)
USBH4_OC_N: J32.4 U13.21 | length 61.2
  Signal_8 w0.125: v2(40.25,37.5) 40.7,37.05 40.7,27.752 41.719,26.733 41.719,25.444 42.47,24.694 42.47,19.069 v2(41.65,18.25)
  Signal_7 w0.125: J32.4@5.75,14 8.5,14 12.5,18 18.905,18 20.953,20.048 23.216,20.048 23.87,19.394 23.87,19.374 24.996,18.248 28.768,18.248 29.52,19 40.25,19 41,18.25 v2(41.65,18.25)
  Bottom w0.125: U13.21@40.25,36.55 v2(40.25,37.5)
USBH4_PWR_EN: J32.5 U13.20 | length 59.3
  Signal_8 w0.125: v2(39.2,37.5) 39.2,35.8 40.1,34.9 40.1,26.967 41.053,26.014 v2(41.053,18.947)
  Signal_7 w0.125: J32.5@5.75,15.25 8.95,15.25 12,18.3 18.849,18.3 20.849,20.3 23.32,20.3 24.122,19.499 24.122,19.479 25.1,18.5 28.664,18.5 29.416,19.252 40.748,19.252 v2(41.053,18.947)
  Bottom w0.125: v2(39.2,37.5) 39.6,37.5 39.75,37.35 U13.20@39.75,36.55
USBH_D_N: U11.AA18 U13.30 | length 23.5
  Top w0.127: v1(62.415,31.915) U11.AA18@63.05,32.55
  Signal_3 w0.165: v2@45.152,35.068 45.373,35.068 45.523,35.218 53.277,35.218 53.827,35.768 55.8,35.768 56.671,36.639 59.381,36.639 62.27,33.751 62.649,33.751 62.981,33.419 62.981,32.481 v1(62.415,31.915)
  Bottom w0.127: U13.30@44.05,34.75 44.096,34.796 44.804,34.796 v2(45.004,34.996)
USBH_D_P: U11.AA17 U13.31 | length 23.7
  Top w0.127: v1(62.3,33) 63.05,33.75 U11.AA17@63.05,33.82
  Signal_3 w0.165: v2(44.9,34.3) 45.125,34.3 45.675,34.85 53.429,34.85 53.979,35.4 55.952,35.4 56.824,36.271 59.229,36.271 61.775,33.725 61.775,33.625 61.05,32.9 61.05,32.525 61.175,32.4 61.7,32.4 v1(62.3,33)
  Bottom w0.127: U13.31@44.05,34.25 v2@44.85,34.25
USER_LED1/IO23: R119.2 U27.33 | length 103.3
  Top w0.125: v1(11.3,63.7) 11.97,63.7 R119.2@12.02,63.75 ; U27.33@53.25,28.8 53.25,26.75 v1(54.25,25.75)
  Signal_3 w0.125: v3(10.251,29.197) 12.031,29.197 12.628,28.6 13,28.6 13.18,28.78 13.194,28.78 13.47,29.056 13.47,29.07 13.6,29.2 14.906,29.2 15.757,28.349 15.757,28.069 16.026,27.8 17.6,27.8 18.6,28.8 18.6,29.341 19.806,30.547 22.015,30.547 22.29,30.272 24.689,30.272 24.889,30.472 27.761,30.472 28.316,31.027 28.927,31.027 29.927,32.028 35.55,32.028 36.805,30.773 37.49,30.773 39.518,32.8 45.826,32.8 46.545,33.519 48.182,33.519 51.148,30.553 52.4,29.301 52.4,27.2 53.85,25.75 v1(54.25,25.75)
  Signal_8 w0.125: v3(10.251,29.197) 10.251,32.093 9.25,33.095 9.25,34.038 11.281,36.069 13.594,36.069 13.869,35.794 13.869,35.681 14.077,35.473 14.279,35.473 14.545,35.207 14.871,35.207 15.75,36.086 15.75,37.086 16.294,37.63 16.569,37.905 16.569,39.189 15.358,40.4 14.534,40.4 14.082,40.852 14.082,46.025 13.455,46.652 13.455,52.145 9.53,56.07 9.53,60.43 11.3,62.2 v1(11.3,63.7)
VCC_LICELL: D13.1 R8.2 U11.B1 | length 55
  Top w0.25: U11.B1@87.18,54.14 87.74,54.7 88.748,54.7 88.879,54.832 90.268,54.832 90.782,54.318 92.418,54.318 93.172,55.072 D13.1@93.172,55.3 94.4,55.3 v1(95.4,54.3)
  Signal_4 w0.5: v1(93.415,12.1) 93.329,12.1 93.457,12.228 93.457,12.772 93.25,12.979 93.25,14.544 94.6,15.894 94.6,20.057 95.7,21.157 95.7,23.4 94.85,24.25 94.85,32.421 95.657,33.228 95.657,36.332 96.275,36.95 96.275,40.625 95.4,41.5 v1(95.4,54.3)
  Bottom w0.25: v1(93.415,12.1) R8.2@94.02,12.1
VCC_MCA: CAD2.1 J11.1 R3.2 R83.2 R97.2 R150.1 R203.2 R261.2 U11.A8 | length 36
  Top w0.25: J11.1@9.468,58.04 11.26,58.04 11.5,57.8 v2(11.5,57.373) ; v1(40.75,67.75) 41.42,67.75 R203.2@41.57,67.6 ; U11.A8@88.45,45.25 89.085,45.885 91.367,45.885 94.5,49.018 94.5,50.35 R261.2@94.3,50.55
  Signal_4 w0.5: v1(14.23,19.143) 17.143,19.143 18.25,20.25 20,20.25 v1(21,19.25) 22.05,18.2 26.807,18.2 v1(27.75,19.143)
  Bottom w0.25: v2(11.5,57.373) 12.135,58.008 CAD2.1@12.135,58.04 13.54,58.04 14.2,58.7 R150.1@14.82,58.7 ; v1(14.23,19.143) R3.2@14.23,21.25 ; v1(21,19.25) R83.2@21,20.27 ; v1(27.75,19.143) R97.2@27.75,20.27
  other v2: 94.5,49.6
VDD_SNVS_IN: R24.1 R25.1 U11.W7 | length 10.8
  Top w0.125: v1(64.955,47.155) U11.W7@65.59,46.52
  Bottom w0.125: R25.1@64.43,55.84 R24.1@65.47,55.84 65.47,47.67 v1(64.955,47.155)
VDDCR1: C40.2 C41.2 C42.2 U16.6 | length 6.1
  Bottom w0.25: C40.2@18.75,30.1 20.14,30.1 C42.2@20.5,30.46 C41.2@20.5,31.44 21.06,31.44 21.3,31.2 21.3,29.8 21.518,29.582 22.018,29.582 U16.6@22.1,29.5
VDDCR2: C52.2 C53.2 C54.2 U24.6 | length 5.1
  Bottom w0.25: C52.2@19.139,48.007 20.093,48.007 20.54,47.56 C54.2@21.1,47.56 C53.2@21.1,48.64 21.76,48.64 22.243,48.157 U24.6@22.739,48.157
VIN: C86.2 FIL1.3 Q1.2 R6.1 R11.2 R126.2 U3.4 U3.8 U26.1 U26.3 | length 48.6
  Top w0.25: 87.9,24 R126.2@88.82,24 88.82,23.22 ; U26.3@92.18,59.787 91.387,59.787 91.2,59.6 91.2,58.2 91.513,57.887 U26.1@92.18,57.887 93.58,57.887 C86.2@93.63,57.937 94.15,57.417 v2(94.15,57.3)
  Signal_4 w0.5: v1(87.2,23.8) 90.4,23.8 93.2,26.6 93.2,35.9 94.375,37.075 94.375,37.639 94.387,37.65 94.387,38.153 94.375,38.165 94.375,40.975 92.75,42.6 92.75,46.814 92.471,47.093 92.249,47.093 91.65,47.692 91.65,51.792 92.75,52.892 92.75,56.561 93.489,57.3 v2(94.15,57.3)
  other v1: 86.5,23.8
VIN_PRESENT: R182.2 R183.2 R184.2 U11.A4 | length 18.5
  Top w0.125: U11.A4@88.45,50.33 v1(88.92,50.8) ; R183.2@90.73,61.207 R184.2@91.77,61.207 91.77,61.83 v2(91.5,62.1) ; R182.2@92.88,56.6 v2@94.125,56.6
  Signal_3 w0.125: v1(88.92,50.8) 88.92,51.326 94.125,56.531 v2(94.125,56.55) 91.5,59.175 v2(91.5,62.1)
VIN_PROT: C1.1 C2.2 C3.2 C11.2 C62.2 C65.1 C111.2 C112.2 C113.2 C121.1 J32.1 R6.2 R101.1 R137.2 R140.2 R148.1 R151.1 R152.1 R269.1 U3.1 U3.2 U3.5 U3.6 U3.7 U5.K U7.3 U12.7 U14.7 U23.3 U23.14 | length 129
  Top w0.25: R269.1@4.25,25.73 4.5,25.48 v2(4.5,25) ; v1(14.63,42.23) R101.1@15.5,42.23 ; U12.7@31.545,29.459 33.401,29.459 C62.2@33.475,29.385 33.475,29.975 v1(33.5,30) ; C121.1@92.66,23.8 92.66,23.652 92.2,23.192 92.2,23.1 v1(91.8,22.7) 92.904,21.596 C2.2@92.904,20.542
  Signal_4 w0.25: v1(50.7,54.8) 54.4,54.8 56.2,53 v1(60.3,53)
  Signal_4 w0.5: J32.1@5.75,10.25 4.65,10.25 3.756,11.144 3.756,13.451 3.3,13.906 3.3,22.737 4.5,23.937 v2(4.5,25) 4.5,25.25 4.907,25.657 5.663,25.657 5.712,25.608 8.537,25.608 10.338,27.409 10.338,27.75 12.065,29.477 12.065,30.242 13.573,31.75 15.25,31.75 16.225,32.725 v1(16.225,32.775) 16.769,32.23 16.769,30.572 17.622,29.72 17.729,29.72 20.591,26.857 21.772,26.857 22.157,26.472 22.157,26.372 22.229,26.3 25.05,26.3 26.025,27.275 30.775,27.275 v1(33.5,30)
  Signal_4 w0.76: v1(14.5,50.25) 15.75,50.25 19.3,53.8 24.3,53.8 25.6,55.1 28.292,55.1 29.392,54 30.498,54 33.198,51.3 35.158,51.3 35.795,50.663 36.405,50.663 37.042,51.3 40.7,51.3 42.737,49.263 44.363,49.263 v1(49.9,54.8)
  Bottom w0.25: v1(14.5,50.25) 15.48,51.23 R152.1@15.48,51.7 ; R151.1@15.48,32.7 15.555,32.775 v1(16.225,32.775) ; U14.7@31.855,32.53 31.855,30.805 32,30.66 32.84,30.66 v1(33.5,30) ; 51,55.4 R137.2@51.77,55.4 ; C113.2@52.5,54.21 52.572,54.282 53.595,54.282 53.627,54.25 U23.3@54.2,54.25 U23.14@55,54.25 ; R140.2@59.58,53 v1(60.3,53) ; U7.3@92.29,23.35 92.15,23.35 91.8,23 v1(91.8,22.7) 92.24,22.7 C11.2@92.74,22.2
  other v1: 87.6,18.7 87.6,19.3 88.2,19.6 88.9,19.6 49.9,55.5 50.7,55.5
